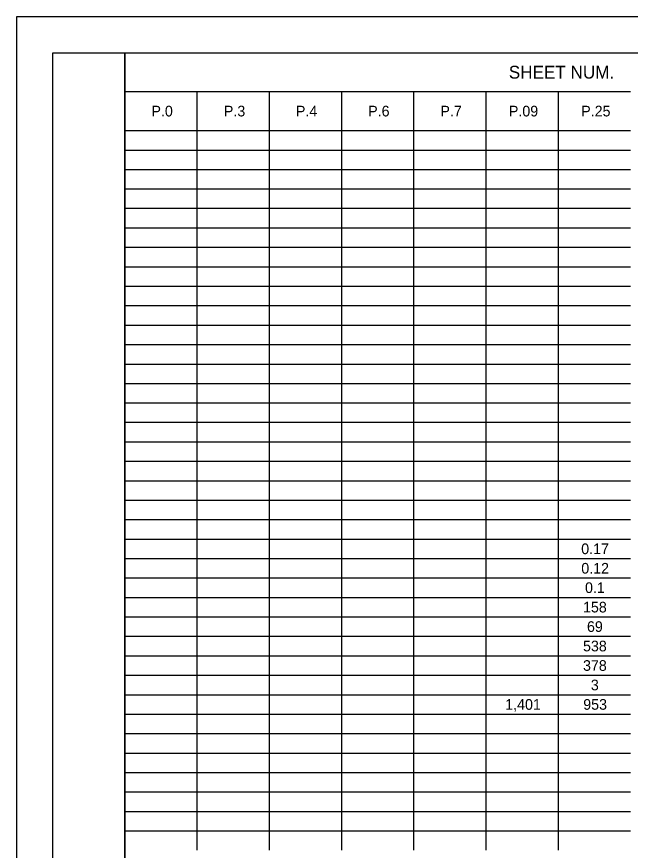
# Model space of a CAD drawing. Extents: x 0 to 34, y 0 to 22.
# Drawn here: x 0 to 8.52, y 10.43 to 22 of the extents above; entities that cross this region are included whole.
import ezdxf

# ---------------------------------------------------------------- set-up
doc = ezdxf.new("R2010")
doc.units = 0
for name, color, linetype in [('SH_Border', 7, 'Continuous'), ('SH_Cut_Line', 7, 'Continuous'), ('SH_Text', 7, 'Continuous')]:
    doc.layers.add(name, color=color, linetype=linetype)

msp = doc.modelspace()

# ---------------------------------------------------------------- linework, layer by layer
at = {"layer": 'SH_Border'}
for points in [[(0.5, 21.5), (1.5, 21.5), (1.5, 0.5), (0.5, 0.5)], [(1.5, 21.5), (33.5, 21.5), (33.5, 0.5), (1.5, 0.5)]]:
    msp.add_lwpolyline(points, close=True, dxfattribs=at)
at = {"layer": 'SH_Cut_Line'}
msp.add_lwpolyline([(0, 0), (34, 0), (34, 22), (0, 22)], close=True, dxfattribs=at)
at = {"layer": 'SH_Text'}
for p, q in [((1.5, 21.5), (2.503, 21.5)), ((1.5, 21.5), (1.5, 21.23)), ((2.503, 21.5), (3.505, 21.5)), ((3.505, 21.5), (4.508, 21.5)), ((4.508, 21.5), (5.51, 21.5)), ((5.51, 21.5), (6.513, 21.5)), ((6.513, 21.5), (7.515, 21.5)), ((7.515, 21.5), (8.518, 21.5)), ((1.5, 21.23), (1.5, 20.96)), ((1.5, 20.96), (2.503, 20.96)), ((1.5, 20.96), (1.5, 20.69)), ((2.503, 20.96), (3.505, 20.96)), ((2.503, 20.96), (2.503, 20.69)), ((3.505, 20.96), (4.508, 20.96)), ((3.505, 20.96), (3.505, 20.69)), ((4.508, 20.96), (5.51, 20.96)), ((4.508, 20.96), (4.508, 20.69)), ((5.51, 20.96), (6.513, 20.96)), ((5.51, 20.96), (5.51, 20.69)), ((6.513, 20.96), (7.515, 20.96)), ((6.513, 20.96), (6.513, 20.69)), ((7.515, 20.96), (8.518, 20.96)), ((7.515, 20.96), (7.515, 20.69)), ((1.5, 20.69), (1.5, 20.42)), ((2.503, 20.69), (2.503, 20.42)), ((3.505, 20.69), (3.505, 20.42)), ((4.508, 20.69), (4.508, 20.42)), ((5.51, 20.69), (5.51, 20.42)), ((6.513, 20.69), (6.513, 20.42)), ((7.515, 20.69), (7.515, 20.42)), ((1.5, 20.42), (2.503, 20.42)), ((1.5, 20.42), (1.5, 20.15)), ((2.503, 20.42), (3.505, 20.42)), ((2.503, 20.42), (2.503, 20.15)), ((3.505, 20.42), (4.508, 20.42)), ((3.505, 20.42), (3.505, 20.15)), ((4.508, 20.42), (5.51, 20.42)), ((4.508, 20.42), (4.508, 20.15)), ((5.51, 20.42), (6.513, 20.42)), ((5.51, 20.42), (5.51, 20.15)), ((6.513, 20.42), (7.515, 20.42)), ((6.513, 20.42), (6.513, 20.15)), ((7.515, 20.42), (8.518, 20.42)), ((7.515, 20.42), (7.515, 20.15)), ((1.5, 20.15), (2.503, 20.15)), ((1.5, 20.15), (1.5, 18.801)), ((2.503, 20.15), (3.505, 20.15)), ((2.503, 20.15), (2.503, 18.801)), ((3.505, 20.15), (4.508, 20.15)), ((3.505, 20.15), (3.505, 18.801)), ((4.508, 20.15), (5.51, 20.15)), ((4.508, 20.15), (4.508, 18.801)), ((5.51, 20.15), (6.513, 20.15)), ((5.51, 20.15), (5.51, 18.801)), ((6.513, 20.15), (7.515, 20.15)), ((6.513, 20.15), (6.513, 18.801)), ((7.515, 20.15), (8.518, 20.15)), ((7.515, 20.15), (7.515, 18.801)), ((1.5, 19.881), (2.503, 19.881)), ((2.503, 19.881), (3.505, 19.881)), ((3.505, 19.881), (4.508, 19.881)), ((4.508, 19.881), (5.51, 19.881)), ((5.51, 19.881), (6.513, 19.881)), ((6.513, 19.881), (7.515, 19.881)), ((7.515, 19.881), (8.518, 19.881)), ((1.5, 19.611), (2.503, 19.611)), ((2.503, 19.611), (3.505, 19.611)), ((3.505, 19.611), (4.508, 19.611)), ((4.508, 19.611), (5.51, 19.611)), ((5.51, 19.611), (6.513, 19.611)), ((6.513, 19.611), (7.515, 19.611)), ((7.515, 19.611), (8.518, 19.611)), ((1.5, 19.341), (2.503, 19.341)), ((2.503, 19.341), (3.505, 19.341)), ((3.505, 19.341), (4.508, 19.341)), ((4.508, 19.341), (5.51, 19.341)), ((5.51, 19.341), (6.513, 19.341)), ((6.513, 19.341), (7.515, 19.341)), ((7.515, 19.341), (8.518, 19.341)), ((1.5, 19.071), (2.503, 19.071)), ((2.503, 19.071), (3.505, 19.071)), ((3.505, 19.071), (4.508, 19.071)), ((4.508, 19.071), (5.51, 19.071)), ((5.51, 19.071), (6.513, 19.071)), ((6.513, 19.071), (7.515, 19.071)), ((7.515, 19.071), (8.518, 19.071)), ((1.5, 18.801), (2.503, 18.801)), ((1.5, 18.801), (1.5, 18.261)), ((2.503, 18.801), (3.505, 18.801)), ((2.503, 18.801), (2.503, 18.261)), ((3.505, 18.801), (4.508, 18.801)), ((3.505, 18.801), (3.505, 18.261)), ((4.508, 18.801), (5.51, 18.801)), ((4.508, 18.801), (4.508, 18.261)), ((5.51, 18.801), (6.513, 18.801)), ((5.51, 18.801), (5.51, 18.261)), ((6.513, 18.801), (7.515, 18.801)), ((6.513, 18.801), (6.513, 18.261)), ((7.515, 18.801), (8.518, 18.801)), ((7.515, 18.801), (7.515, 18.261)), ((1.5, 18.531), (2.503, 18.531)), ((2.503, 18.531), (3.505, 18.531)), ((3.505, 18.531), (4.508, 18.531)), ((4.508, 18.531), (5.51, 18.531)), ((5.51, 18.531), (6.513, 18.531)), ((6.513, 18.531), (7.515, 18.531)), ((7.515, 18.531), (8.518, 18.531)), ((1.5, 18.261), (2.503, 18.261)), ((1.5, 18.261), (1.5, 17.991)), ((2.503, 18.261), (3.505, 18.261)), ((2.503, 18.261), (2.503, 17.991)), ((3.505, 18.261), (4.508, 18.261)), ((3.505, 18.261), (3.505, 17.991)), ((4.508, 18.261), (5.51, 18.261)), ((4.508, 18.261), (4.508, 17.991)), ((5.51, 18.261), (6.513, 18.261)), ((5.51, 18.261), (5.51, 17.991)), ((6.513, 18.261), (7.515, 18.261)), ((6.513, 18.261), (6.513, 17.991)), ((7.515, 18.261), (8.518, 18.261)), ((7.515, 18.261), (7.515, 17.991)), ((1.5, 17.991), (2.503, 17.991)), ((1.5, 17.991), (1.5, 17.721)), ((2.503, 17.991), (3.505, 17.991)), ((2.503, 17.991), (2.503, 17.721)), ((3.505, 17.991), (4.508, 17.991)), ((3.505, 17.991), (3.505, 17.721)), ((4.508, 17.991), (5.51, 17.991)), ((4.508, 17.991), (4.508, 17.721)), ((5.51, 17.991), (6.513, 17.991)), ((5.51, 17.991), (5.51, 17.721)), ((6.513, 17.991), (7.515, 17.991)), ((6.513, 17.991), (6.513, 17.721)), ((7.515, 17.991), (8.518, 17.991)), ((7.515, 17.991), (7.515, 17.721)), ((1.5, 17.721), (2.503, 17.721)), ((1.5, 17.721), (1.5, 17.451)), ((2.503, 17.721), (3.505, 17.721)), ((2.503, 17.721), (2.503, 17.451)), ((3.505, 17.721), (4.508, 17.721)), ((3.505, 17.721), (3.505, 17.451)), ((4.508, 17.721), (5.51, 17.721)), ((4.508, 17.721), (4.508, 17.451)), ((5.51, 17.721), (6.513, 17.721)), ((5.51, 17.721), (5.51, 17.451)), ((6.513, 17.721), (7.515, 17.721)), ((6.513, 17.721), (6.513, 17.451)), ((7.515, 17.721), (8.518, 17.721)), ((7.515, 17.721), (7.515, 17.451)), ((1.5, 17.451), (2.503, 17.451)), ((1.5, 17.451), (1.5, 17.181)), ((2.503, 17.451), (3.505, 17.451)), ((2.503, 17.451), (2.503, 17.181)), ((3.505, 17.451), (4.508, 17.451)), ((3.505, 17.451), (3.505, 17.181)), ((4.508, 17.451), (5.51, 17.451)), ((4.508, 17.451), (4.508, 17.181)), ((5.51, 17.451), (6.513, 17.451)), ((5.51, 17.451), (5.51, 17.181)), ((6.513, 17.451), (7.515, 17.451)), ((6.513, 17.451), (6.513, 17.181)), ((7.515, 17.451), (8.518, 17.451)), ((7.515, 17.451), (7.515, 17.181)), ((1.5, 17.181), (2.503, 17.181)), ((1.5, 17.181), (1.5, 16.912)), ((2.503, 17.181), (3.505, 17.181)), ((2.503, 17.181), (2.503, 16.912)), ((3.505, 17.181), (4.508, 17.181)), ((3.505, 17.181), (3.505, 16.912)), ((4.508, 17.181), (5.51, 17.181)), ((4.508, 17.181), (4.508, 16.912)), ((5.51, 17.181), (6.513, 17.181)), ((5.51, 17.181), (5.51, 16.912)), ((6.513, 17.181), (7.515, 17.181)), ((6.513, 17.181), (6.513, 16.912)), ((7.515, 17.181), (8.518, 17.181)), ((7.515, 17.181), (7.515, 16.912)), ((1.5, 16.912), (2.503, 16.912)), ((1.5, 16.912), (1.5, 16.372)), ((2.503, 16.912), (3.505, 16.912)), ((2.503, 16.912), (2.503, 16.372)), ((3.505, 16.912), (4.508, 16.912)), ((3.505, 16.912), (3.505, 16.372)), ((4.508, 16.912), (5.51, 16.912)), ((4.508, 16.912), (4.508, 16.372)), ((5.51, 16.912), (6.513, 16.912)), ((5.51, 16.912), (5.51, 16.372)), ((6.513, 16.912), (7.515, 16.912)), ((6.513, 16.912), (6.513, 16.372)), ((7.515, 16.912), (8.518, 16.912)), ((7.515, 16.912), (7.515, 16.372)), ((1.5, 16.642), (2.503, 16.642)), ((2.503, 16.642), (3.505, 16.642)), ((3.505, 16.642), (4.508, 16.642)), ((4.508, 16.642), (5.51, 16.642)), ((5.51, 16.642), (6.513, 16.642)), ((6.513, 16.642), (7.515, 16.642)), ((7.515, 16.642), (8.518, 16.642)), ((1.5, 16.372), (2.503, 16.372)), ((1.5, 16.372), (1.5, 16.102)), ((2.503, 16.372), (3.505, 16.372)), ((2.503, 16.372), (2.503, 16.102)), ((3.505, 16.372), (4.508, 16.372)), ((3.505, 16.372), (3.505, 16.102)), ((4.508, 16.372), (5.51, 16.372)), ((4.508, 16.372), (4.508, 16.102)), ((5.51, 16.372), (6.513, 16.372)), ((5.51, 16.372), (5.51, 16.102)), ((6.513, 16.372), (7.515, 16.372)), ((6.513, 16.372), (6.513, 16.102)), ((7.515, 16.372), (8.518, 16.372)), ((7.515, 16.372), (7.515, 16.102)), ((1.5, 16.102), (2.503, 16.102)), ((1.5, 16.102), (1.5, 15.832)), ((2.503, 16.102), (3.505, 16.102)), ((2.503, 16.102), (2.503, 15.832)), ((3.505, 16.102), (4.508, 16.102)), ((3.505, 16.102), (3.505, 15.832)), ((4.508, 16.102), (5.51, 16.102)), ((4.508, 16.102), (4.508, 15.832)), ((5.51, 16.102), (6.513, 16.102)), ((5.51, 16.102), (5.51, 15.832)), ((6.513, 16.102), (7.515, 16.102)), ((6.513, 16.102), (6.513, 15.832)), ((7.515, 16.102), (8.518, 16.102)), ((7.515, 16.102), (7.515, 15.832)), ((1.5, 15.832), (2.503, 15.832)), ((1.5, 15.832), (1.5, 15.562)), ((2.503, 15.832), (3.505, 15.832)), ((2.503, 15.832), (2.503, 15.562)), ((3.505, 15.832), (4.508, 15.832)), ((3.505, 15.832), (3.505, 15.562)), ((4.508, 15.832), (5.51, 15.832)), ((4.508, 15.832), (4.508, 15.562)), ((5.51, 15.832), (6.513, 15.832)), ((5.51, 15.832), (5.51, 15.562)), ((6.513, 15.832), (7.515, 15.832)), ((6.513, 15.832), (6.513, 15.562)), ((7.515, 15.832), (8.518, 15.832)), ((7.515, 15.832), (7.515, 15.562)), ((1.5, 15.562), (2.503, 15.562)), ((1.5, 15.562), (1.5, 15.022)), ((2.503, 15.562), (3.505, 15.562)), ((2.503, 15.562), (2.503, 15.022)), ((3.505, 15.562), (4.508, 15.562)), ((3.505, 15.562), (3.505, 15.022)), ((4.508, 15.562), (5.51, 15.562)), ((4.508, 15.562), (4.508, 15.022)), ((5.51, 15.562), (6.513, 15.562)), ((5.51, 15.562), (5.51, 15.022)), ((6.513, 15.562), (7.515, 15.562)), ((6.513, 15.562), (6.513, 15.022)), ((7.515, 15.562), (8.518, 15.562)), ((7.515, 15.562), (7.515, 15.022)), ((1.5, 15.292), (2.503, 15.292)), ((2.503, 15.292), (3.505, 15.292)), ((3.505, 15.292), (4.508, 15.292)), ((4.508, 15.292), (5.51, 15.292)), ((5.51, 15.292), (6.513, 15.292)), ((6.513, 15.292), (7.515, 15.292)), ((7.515, 15.292), (8.518, 15.292)), ((1.5, 15.022), (2.503, 15.022)), ((1.5, 15.022), (1.5, 14.752)), ((2.503, 15.022), (3.505, 15.022)), ((2.503, 15.022), (2.503, 14.752)), ((3.505, 15.022), (4.508, 15.022)), ((3.505, 15.022), (3.505, 14.752)), ((4.508, 15.022), (5.51, 15.022)), ((4.508, 15.022), (4.508, 14.752)), ((5.51, 15.022), (6.513, 15.022)), ((5.51, 15.022), (5.51, 14.752)), ((6.513, 15.022), (7.515, 15.022)), ((6.513, 15.022), (6.513, 14.752)), ((7.515, 15.022), (8.518, 15.022)), ((7.515, 15.022), (7.515, 14.752)), ((1.5, 14.752), (2.503, 14.752)), ((1.5, 14.752), (1.5, 14.482)), ((2.503, 14.752), (3.505, 14.752)), ((2.503, 14.752), (2.503, 14.482)), ((3.505, 14.752), (4.508, 14.752)), ((3.505, 14.752), (3.505, 14.482)), ((4.508, 14.752), (5.51, 14.752)), ((4.508, 14.752), (4.508, 14.482)), ((5.51, 14.752), (6.513, 14.752)), ((5.51, 14.752), (5.51, 14.482)), ((6.513, 14.752), (7.515, 14.752)), ((6.513, 14.752), (6.513, 14.482)), ((7.515, 14.752), (8.518, 14.752)), ((7.515, 14.752), (7.515, 14.482)), ((1.5, 14.482), (2.503, 14.482)), ((1.5, 14.482), (1.5, 14.212)), ((2.503, 14.482), (3.505, 14.482)), ((2.503, 14.482), (2.503, 14.212)), ((3.505, 14.482), (4.508, 14.482)), ((3.505, 14.482), (3.505, 14.212)), ((4.508, 14.482), (5.51, 14.482)), ((4.508, 14.482), (4.508, 14.212)), ((5.51, 14.482), (6.513, 14.482)), ((5.51, 14.482), (5.51, 14.212)), ((6.513, 14.482), (7.515, 14.482)), ((6.513, 14.482), (6.513, 14.212)), ((7.515, 14.482), (8.518, 14.482)), ((7.515, 14.482), (7.515, 14.212)), ((1.5, 14.212), (2.503, 14.212)), ((1.5, 14.212), (1.5, 12.053)), ((2.503, 14.212), (3.505, 14.212)), ((2.503, 14.212), (2.503, 12.053)), ((3.505, 14.212), (4.508, 14.212)), ((3.505, 14.212), (3.505, 12.053)), ((4.508, 14.212), (5.51, 14.212)), ((4.508, 14.212), (4.508, 12.053)), ((5.51, 14.212), (6.513, 14.212)), ((5.51, 14.212), (5.51, 12.053)), ((6.513, 14.212), (7.515, 14.212)), ((6.513, 14.212), (6.513, 12.053)), ((7.515, 14.212), (8.518, 14.212)), ((7.515, 14.212), (7.515, 12.053)), ((1.5, 13.942), (2.503, 13.942)), ((2.503, 13.942), (3.505, 13.942)), ((3.505, 13.942), (4.508, 13.942)), ((4.508, 13.942), (5.51, 13.942)), ((5.51, 13.942), (6.513, 13.942)), ((6.513, 13.942), (7.515, 13.942)), ((7.515, 13.942), (8.518, 13.942)), ((1.5, 13.673), (2.503, 13.673)), ((2.503, 13.673), (3.505, 13.673)), ((3.505, 13.673), (4.508, 13.673)), ((4.508, 13.673), (5.51, 13.673)), ((5.51, 13.673), (6.513, 13.673)), ((6.513, 13.673), (7.515, 13.673)), ((7.515, 13.673), (8.518, 13.673)), ((1.5, 13.403), (2.503, 13.403)), ((2.503, 13.403), (3.505, 13.403)), ((3.505, 13.403), (4.508, 13.403)), ((4.508, 13.403), (5.51, 13.403)), ((5.51, 13.403), (6.513, 13.403)), ((6.513, 13.403), (7.515, 13.403)), ((7.515, 13.403), (8.518, 13.403)), ((1.5, 13.133), (2.503, 13.133)), ((2.503, 13.133), (3.505, 13.133)), ((3.505, 13.133), (4.508, 13.133)), ((4.508, 13.133), (5.51, 13.133)), ((5.51, 13.133), (6.513, 13.133)), ((6.513, 13.133), (7.515, 13.133)), ((7.515, 13.133), (8.518, 13.133)), ((1.5, 12.863), (2.503, 12.863)), ((2.503, 12.863), (3.505, 12.863)), ((3.505, 12.863), (4.508, 12.863)), ((4.508, 12.863), (5.51, 12.863)), ((5.51, 12.863), (6.513, 12.863)), ((6.513, 12.863), (7.515, 12.863)), ((7.515, 12.863), (8.518, 12.863)), ((1.5, 12.593), (2.503, 12.593)), ((2.503, 12.593), (3.505, 12.593)), ((3.505, 12.593), (4.508, 12.593)), ((4.508, 12.593), (5.51, 12.593)), ((5.51, 12.593), (6.513, 12.593)), ((6.513, 12.593), (7.515, 12.593)), ((7.515, 12.593), (8.518, 12.593)), ((1.5, 12.323), (2.503, 12.323)), ((2.503, 12.323), (3.505, 12.323)), ((3.505, 12.323), (4.508, 12.323)), ((4.508, 12.323), (5.51, 12.323)), ((5.51, 12.323), (6.513, 12.323)), ((6.513, 12.323), (7.515, 12.323)), ((7.515, 12.323), (8.518, 12.323)), ((1.5, 12.053), (2.503, 12.053)), ((1.5, 12.053), (1.5, 11.783)), ((2.503, 12.053), (3.505, 12.053)), ((2.503, 12.053), (2.503, 11.783)), ((3.505, 12.053), (4.508, 12.053)), ((3.505, 12.053), (3.505, 11.783)), ((4.508, 12.053), (5.51, 12.053)), ((4.508, 12.053), (4.508, 11.783)), ((5.51, 12.053), (6.513, 12.053)), ((5.51, 12.053), (5.51, 11.783)), ((6.513, 12.053), (7.515, 12.053)), ((6.513, 12.053), (6.513, 11.783)), ((7.515, 12.053), (8.518, 12.053)), ((7.515, 12.053), (7.515, 11.783)), ((1.5, 11.783), (2.503, 11.783)), ((1.5, 11.783), (1.5, 10.704)), ((2.503, 11.783), (3.505, 11.783)), ((2.503, 11.783), (2.503, 10.704)), ((3.505, 11.783), (4.508, 11.783)), ((3.505, 11.783), (3.505, 10.704)), ((4.508, 11.783), (5.51, 11.783)), ((4.508, 11.783), (4.508, 10.704)), ((5.51, 11.783), (6.513, 11.783)), ((5.51, 11.783), (5.51, 10.704)), ((6.513, 11.783), (7.515, 11.783)), ((6.513, 11.783), (6.513, 10.704)), ((7.515, 11.783), (8.518, 11.783)), ((7.515, 11.783), (7.515, 10.704)), ((1.5, 11.513), (2.503, 11.513)), ((2.503, 11.513), (3.505, 11.513)), ((3.505, 11.513), (4.508, 11.513)), ((4.508, 11.513), (5.51, 11.513)), ((5.51, 11.513), (6.513, 11.513)), ((6.513, 11.513), (7.515, 11.513)), ((7.515, 11.513), (8.518, 11.513)), ((1.5, 11.243), (2.503, 11.243)), ((2.503, 11.243), (3.505, 11.243)), ((3.505, 11.243), (4.508, 11.243)), ((4.508, 11.243), (5.51, 11.243)), ((5.51, 11.243), (6.513, 11.243)), ((6.513, 11.243), (7.515, 11.243)), ((7.515, 11.243), (8.518, 11.243)), ((1.5, 10.973), (2.503, 10.973)), ((2.503, 10.973), (3.505, 10.973)), ((3.505, 10.973), (4.508, 10.973)), ((4.508, 10.973), (5.51, 10.973)), ((5.51, 10.973), (6.513, 10.973)), ((6.513, 10.973), (7.515, 10.973)), ((7.515, 10.973), (8.518, 10.973)), ((1.5, 10.704), (2.503, 10.704)), ((1.5, 10.704), (1.5, 10.434)), ((2.503, 10.704), (3.505, 10.704)), ((2.503, 10.704), (2.503, 10.434)), ((3.505, 10.704), (4.508, 10.704)), ((3.505, 10.704), (3.505, 10.434)), ((4.508, 10.704), (5.51, 10.704)), ((4.508, 10.704), (4.508, 10.434)), ((5.51, 10.704), (6.513, 10.704)), ((5.51, 10.704), (5.51, 10.434)), ((6.513, 10.704), (7.515, 10.704)), ((6.513, 10.704), (6.513, 10.434)), ((7.515, 10.704), (8.518, 10.704)), ((7.515, 10.704), (7.515, 10.434))]:
    msp.add_line(p, q, dxfattribs=at)

# ---------------------------------------------------------------- texts
for s, height, p in [('SHEET NUM.', 0.1774, (6.831, 21.141)), ('P.0', 0.1478, (1.871, 20.616)), ('P.3', 0.1478, (2.876, 20.616)), ('P.4', 0.1478, (3.876, 20.616)), ('P.6', 0.1478, (4.879, 20.616)), ('P.7', 0.1478, (5.882, 20.616)), ('P.09', 0.1478, (6.832, 20.616)), ('P.25', 0.1478, (7.836, 20.616)), ('0.17', 0.1478, (7.836, 14.543)), ('0.12', 0.1478, (7.837, 14.273)), ('0.1', 0.1478, (7.889, 14.004)), ('158', 0.1478, (7.861, 13.734)), ('69', 0.1478, (7.916, 13.464)), ('538', 0.1478, (7.861, 13.194)), ('378', 0.1478, (7.861, 12.924)), ('3', 0.148, (7.97, 12.654)), ('1,401', 0.1478, (6.781, 12.384)), ('953', 0.1478, (7.864, 12.384))]:
    msp.add_text(s, height=height, dxfattribs=at).set_placement(p)

doc.saveas('drawing.dxf')
